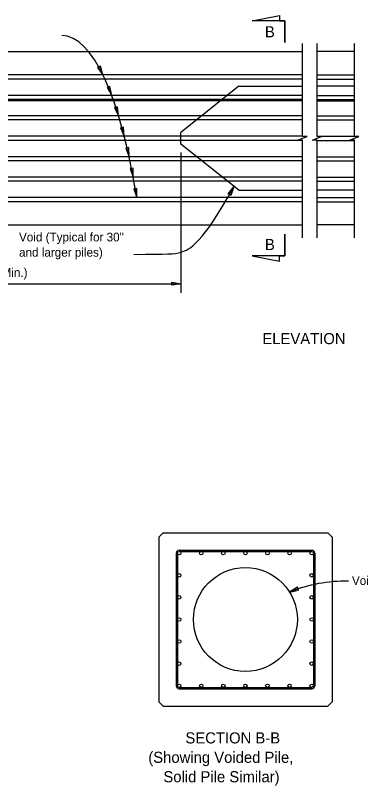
# Model space of a CAD drawing. Extents: x 0 to 36.1, y -3.7 to 15.
# Drawn here: x 6.87 to 10.86, y 3.9 to 12.79 of the extents above; entities that cross this region are included whole.
import ezdxf

# ---------------------------------------------------------------- set-up
doc = ezdxf.new("R2010")
doc.units = 0
for name, color, linetype in [('Dimension', 7, 'Continuous'), ('Leader', 7, 'Continuous'), ('Miscellaneous', 7, 'Continuous'), ('PileConc', 7, 'Continuous'), ('PileConc_h', 7, 'Continuous'), ('PrestressSteel', 7, 'Continuous'), ('Symbols', 7, 'Continuous'), ('TextStructures', 7, 'Continuous')]:
    doc.layers.add(name, color=color, linetype=linetype)

msp = doc.modelspace()

# ---------------------------------------------------------------- linework, layer by layer
at = {"layer": 'Dimension'}
for p, q in [((8.7785, 11.2066), (8.7785, 9.5876)), ((4.7785, 9.6904), (8.7785, 9.6904))]:
    msp.add_line(p, q, dxfattribs=at)
for points in [[(10.1834, 10.2207), (10.1834, 11.3468), (10.1317, 11.3468), (10.1834, 11.3693), (10.235, 11.3918), (10.1834, 11.3918), (10.1834, 12.4621)], [(10.35, 10.2207), (10.35, 11.3468), (10.2983, 11.3468), (10.35, 11.3693), (10.4016, 11.3918), (10.35, 11.3918), (10.35, 12.4621)], [(10.7805, 10.2207), (10.7805, 11.3468), (10.7289, 11.3468), (10.7805, 11.3693), (10.8322, 11.3918), (10.7805, 11.3918), (10.7805, 12.4621)]]:
    msp.add_lwpolyline(points, dxfattribs=at)
for points in [[(7.8779, 12.1005), (7.8479, 12.2017), (7.8162, 12.1862)], [(7.9787, 11.8645), (7.9586, 11.9682), (7.9256, 11.9558)], [(8.0585, 11.6286), (8.045, 11.7333), (8.0112, 11.723)], [(8.1244, 11.3927), (8.1157, 11.4979), (8.0815, 11.4892)], [(8.1799, 11.1568), (8.1751, 11.2623), (8.1406, 11.2548)], [(8.2272, 10.9208), (8.2256, 11.0264), (8.1909, 11.02)], [(8.2676, 10.685), (8.2687, 10.7906), (8.2339, 10.7851)], [(8.7785, 9.6904), (8.6744, 9.6728), (8.6744, 9.7081)], [(10.0323, 6.1335), (10.1355, 6.156), (10.1223, 6.1888)]]:
    msp.add_lwpolyline(points, close=True, dxfattribs=at)
msp.add_open_spline([(8.2331, 10.0289), (8.6457, 10.038), (8.7281, 10.0179), (9.0272, 10.1508), (9.3872, 10.8099)], degree=3, dxfattribs=at)
at = {"layer": 'Leader'}
msp.add_arc((10.6849, 4.5123), 1.7476, 89.13531, 111.92522, dxfattribs=at)
msp.add_ellipse((7.3706, 8.4669), major_axis=(-0.0321, -4.0884), ratio=0.256409, start_param=2.146255, end_param=3.141593, dxfattribs=at)
at = {"layer": 'Miscellaneous'}
for p, q in [((10.1834, 11.8176), (5.5842, 11.8176)), ((10.1834, 11.8026), (5.5842, 11.8026)), ((10.35, 11.8176), (10.7805, 11.8176)), ((10.35, 11.8026), (10.7805, 11.8026))]:
    msp.add_line(p, q, dxfattribs=at)
at = {"layer": 'PileConc'}
for p, q in [((0.841, 12.3693), (10.1834, 12.3693)), ((10.7805, 12.3693), (10.35, 12.3693)), ((0.841, 10.3693), (10.1834, 10.3693)), ((10.7805, 10.3693), (10.35, 10.3693)), ((8.5725, 6.8172), (8.5225, 6.7672)), ((8.5225, 6.7672), (8.5225, 4.8672)), ((8.5725, 6.8172), (10.4725, 6.8172)), ((10.4725, 6.8172), (10.5225, 6.7672)), ((10.5225, 6.7672), (10.5225, 4.8672)), ((8.5225, 4.8672), (8.5725, 4.8172)), ((8.5725, 4.8172), (10.4725, 4.8172)), ((10.4725, 4.8172), (10.5225, 4.8672))]:
    msp.add_line(p, q, dxfattribs=at)
msp.add_circle((9.5224, 5.8172), 0.6, dxfattribs=at)
at = {"layer": 'PileConc_h'}
for p, q in [((9.4452, 11.9693), (8.7785, 11.4359)), ((9.4452, 11.9693), (10.1834, 11.9693)), ((10.7805, 11.9693), (10.35, 11.9693)), ((8.7785, 11.3026), (8.7785, 11.4359)), ((9.4452, 10.7693), (8.7785, 11.3026)), ((9.4452, 10.7693), (10.1834, 10.7693)), ((10.7805, 10.7693), (10.35, 10.7693))]:
    msp.add_line(p, q, dxfattribs=at)
at = {"layer": 'PrestressSteel'}
for p, q in [((10.1834, 12.1005), (0.7785, 12.1005)), ((10.35, 12.1005), (10.7805, 12.1005)), ((10.1834, 12.0536), (5.1518, 12.0536)), ((10.35, 12.0536), (10.7805, 12.0536)), ((10.1834, 11.8645), (5.1137, 11.8645)), ((10.35, 11.8645), (10.7805, 11.8645)), ((10.1834, 11.8176), (5.1187, 11.8176)), ((10.35, 11.8176), (10.7805, 11.8176)), ((10.1834, 11.5817), (5.3401, 11.5817)), ((10.1834, 11.6286), (5.3518, 11.6286)), ((10.35, 11.6286), (10.7805, 11.6286)), ((10.35, 11.5817), (10.7805, 11.5817)), ((10.1834, 11.3927), (5.216, 11.3927)), ((10.35, 11.3927), (10.7805, 11.3927)), ((10.1834, 11.3458), (5.2267, 11.3458)), ((10.35, 11.3458), (10.7805, 11.3458)), ((10.1834, 11.1568), (5.1137, 11.1568)), ((10.1834, 11.1099), (5.1137, 11.1099)), ((10.35, 11.1568), (10.7805, 11.1568)), ((10.35, 11.1099), (10.7805, 11.1099)), ((10.1834, 10.9208), (5.1137, 10.9208)), ((10.1834, 10.8739), (5.1137, 10.8739)), ((10.35, 10.9208), (10.7805, 10.9208)), ((10.35, 10.8739), (10.7805, 10.8739)), ((10.1834, 10.685), (5.1125, 10.685)), ((10.35, 10.685), (10.7805, 10.685)), ((10.1834, 10.6381), (0.7785, 10.6381)), ((10.35, 10.6381), (10.7805, 10.6381)), ((8.7225, 6.5822), (8.7225, 5.0523)), ((8.7375, 6.5822), (8.7375, 5.0523)), ((8.7575, 6.6172), (10.2875, 6.6172)), ((8.7575, 6.6022), (10.2875, 6.6022)), ((10.3074, 6.5822), (10.3074, 5.0523)), ((10.3225, 6.5822), (10.3225, 5.0523)), ((8.7575, 5.0323), (10.2875, 5.0323)), ((8.7575, 5.0172), (10.2875, 5.0172))]:
    msp.add_line(p, q, dxfattribs=at)
for centre in [(8.7575, 6.5822), (9.0125, 6.5822), (9.2675, 6.5822), (9.5224, 6.5822), (9.7774, 6.5822), (10.0324, 6.5822), (10.2874, 6.5822), (8.7575, 6.3272), (10.2874, 6.3272), (8.7575, 6.0722), (10.2874, 6.0722), (8.7575, 5.8172), (10.2874, 5.8172), (8.7575, 5.5623), (10.2874, 5.5623), (8.7575, 5.3073), (10.2874, 5.3073), (8.7575, 5.0523), (9.0125, 5.0523), (9.2675, 5.0523), (9.5224, 5.0523), (9.7774, 5.0523), (10.0324, 5.0523), (10.2874, 5.0523)]:
    msp.add_circle(centre, 0.02, dxfattribs=at)
for centre, start, end in [((8.7575, 6.5822), 90, 180), ((10.2874, 6.5822), 0, 90), ((8.7575, 5.0523), 180, 270), ((10.2874, 5.0523), 270, 0)]:
    msp.add_arc(centre, 0.035, start, end, dxfattribs=at)
at = {"layer": 'Symbols'}
for points in [[(9.9774, 12.475), (9.9774, 12.725), (9.6024, 12.725), (9.9149, 12.7875), (9.9149, 12.725), (9.9774, 12.725)], [(9.3218, 10.727), (9.3872, 10.8099), (9.3527, 10.7101)], [(9.9774, 10.2635), (9.9774, 10.0135), (9.6024, 10.0135), (9.9149, 9.951), (9.9149, 10.0135), (9.9774, 10.0135)]]:
    msp.add_lwpolyline(points, close=True, dxfattribs=at)

# ---------------------------------------------------------------- texts
at = {"layer": 'Dimension'}
for s, p in [('Void (Typical for 30" ', (6.9092, 10.1795)), ('and larger piles)', (6.9092, 10.0035)), ('Void', (10.7523, 6.2153))]:
    msp.add_text(s, height=0.1008, dxfattribs=at).set_placement(p)
at = {"layer": 'TextStructures'}
for s, height, p in [('B', 0.128, (9.7478, 12.5343)), ('B', 0.128, (9.7478, 10.0799)), ('2D (Min.)', 0.1008, (6.4531, 9.7702)), ('ELEVATION', 0.128, (9.7181, 8.994)), ('SECTION B-B', 0.128, (8.8297, 4.3867)), ('(Showing Voided Pile,', 0.128, (8.4014, 4.1627)), ('Solid Pile Similar)', 0.128, (8.5757, 3.9387))]:
    msp.add_text(s, height=height, dxfattribs=at).set_placement(p)

doc.saveas('drawing.dxf')
